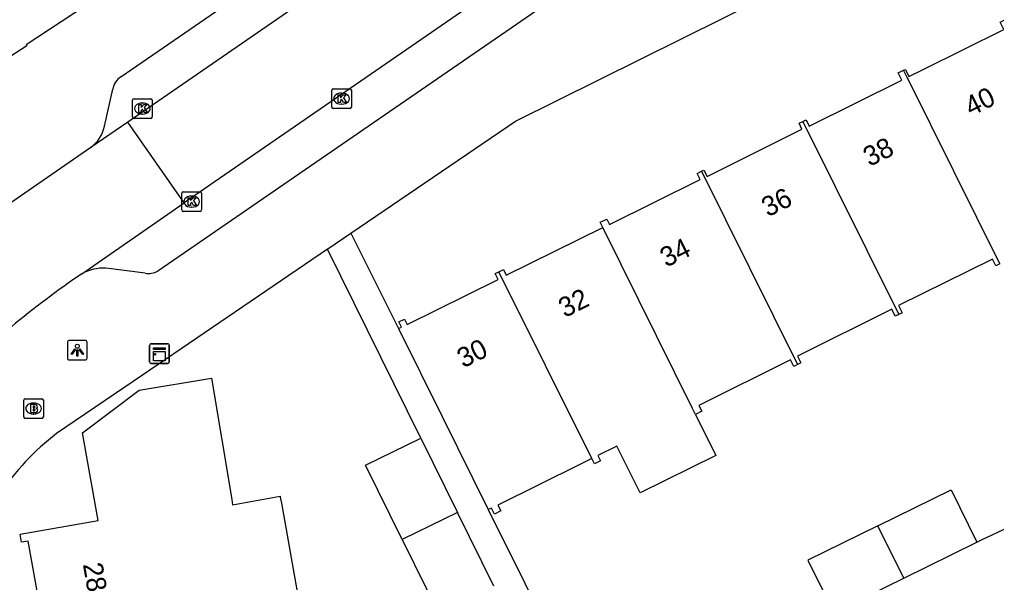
# Model space of a CAD drawing. Extents: x 157793 to 159380, y 380882 to 382313.
# Drawn here: x 158230.61 to 158280.29, y 381421.49 to 381450.14 of the extents above; entities that cross this region are included whole.
import ezdxf

# ---------------------------------------------------------------- set-up
doc = ezdxf.new("R2010")
doc.units = 0
for name, color, linetype in [('IMGEO_Brandkraan', 7, 'Continuous'), ('IMGEO_Kast', 7, 'Continuous'), ('IMGEO_Kolk', 7, 'Continuous'), ('IMGEO_Lichtpunt', 7, 'Continuous'), ('IMGEO_Pand', 7, 'Continuous'), ('IMGEO_Pand_nummerreeks', 7, 'Continuous'), ('IMGEO_Rijbaan_lokaal_open', 7, 'Continuous'), ('IMGEO_Voetpad_open', 7, 'Continuous')]:
    doc.layers.add(name, color=color, linetype=linetype)

msp = doc.modelspace()

# ---------------------------------------------------------------- linework, layer by layer
at = {"layer": 'IMGEO_Brandkraan'}
for p, q in [((158230.824, 381429.92), (158230.824, 381430.772)), ((158230.899, 381430.846), (158231.751, 381430.846)), ((158231.312, 381430.626), (158231.337, 381430.626)), ((158231.825, 381430.772), (158231.825, 381429.92)), ((158231.335, 381430.066), (158231.31, 381430.066)), ((158231.751, 381429.846), (158230.899, 381429.846))]:
    msp.add_line(p, q, dxfattribs=at)
for points in [[(158230.824, 381429.92), (158230.824, 381430.772)], [(158230.899, 381430.846), (158231.751, 381430.846)], [(158231.172, 381430.546), (158231.172, 381430.146), (158231.385, 381430.146)], [(158231.403, 381430.546), (158231.172, 381430.546)], [(158231.825, 381430.772), (158231.825, 381429.92)], [(158231.351, 381430.465), (158231.297, 381430.465), (158231.297, 381430.389)], [(158231.297, 381430.389), (158231.35, 381430.389)], [(158231.359, 381430.313), (158231.297, 381430.313), (158231.297, 381430.232)], [(158231.297, 381430.232), (158231.359, 381430.232)], [(158231.751, 381429.846), (158230.899, 381429.846)]]:
    msp.add_lwpolyline(points, dxfattribs=at)
for centre, radius, start, end in [((158230.901, 381430.77), 0.0765, 91.552, 178.448), ((158230.901, 381430.77), 0.0765, 91.552, 178.448), ((158231.407, 381430.401), 0.145, 59.4692, 91.5367), ((158231.432, 381430.448), 0.0922, 285.5137, 58.1501), ((158231.749, 381430.77), 0.0765, 1.552, 88.448), ((158231.749, 381430.77), 0.0765, 1.552, 88.448), ((158231.352, 381430.427), 0.0379, 267.8285, 90.9355), ((158231.36, 381430.272), 0.0404, 269.8759, 90.5077), ((158231.391, 381430.397), 0.251, 268.6676, 293.5347), ((158231.437, 381430.256), 0.105, 301.3115, 78.989), ((158230.901, 381429.922), 0.0765, 181.552, 268.448), ((158230.901, 381429.922), 0.0765, 181.552, 268.448), ((158231.749, 381429.922), 0.0765, 271.552, 358.448), ((158231.749, 381429.922), 0.0765, 271.552, 358.448)]:
    msp.add_arc(centre, radius, start, end, dxfattribs=at)
for centre, major_axis, ratio, start_param, end_param in [((158231.311, 381430.346), (-0.387, 0.002), 0.722429, 4.712389, 7.853982), ((158231.336, 381430.346), (-0.39, 0.002), 0.717154, 1.570796, 4.712389)]:
    msp.add_ellipse(centre, major_axis=major_axis, ratio=ratio, start_param=start_param, end_param=end_param, dxfattribs=at)
at = {"layer": 'IMGEO_Kast'}
for p, q in [((158237.228, 381432.715), (158237.228, 381433.556)), ((158237.228, 381433.556), (158237.228, 381432.715)), ((158237.303, 381433.64), (158238.144, 381433.64)), ((158238.144, 381433.64), (158237.303, 381433.64)), ((158238.228, 381433.565), (158238.228, 381432.724)), ((158238.228, 381432.724), (158238.228, 381433.565)), ((158238.153, 381432.64), (158237.312, 381432.64)), ((158237.312, 381432.64), (158238.153, 381432.64))]:
    msp.add_line(p, q, dxfattribs=at)
for points in [[(158237.423, 381433.43), (158238.023, 381433.43), (158238.023, 381433.345), (158237.423, 381433.345), (158237.423, 381433.43)], [(158237.423, 381433.255), (158238.023, 381433.255), (158238.023, 381432.766), (158237.423, 381432.766), (158237.423, 381433.255)]]:
    msp.add_lwpolyline(points, dxfattribs=at)
msp.add_circle((158237.507, 381433.104), 0.0377, dxfattribs=at)
for centre, start, end in [((158237.306, 381433.562), 92.4484, 184.2845), ((158237.306, 381433.562), 92.4484, 184.2845), ((158238.15, 381433.562), 2.4484, 94.2845), ((158238.15, 381433.562), 2.4484, 94.2845), ((158237.306, 381432.718), 182.4484, 274.2845), ((158237.306, 381432.718), 182.4484, 274.2845), ((158238.15, 381432.718), 272.4484, 4.2845), ((158238.15, 381432.718), 272.4484, 4.2845)]:
    msp.add_arc(centre, 0.0779, start, end, dxfattribs=at)
at = {"layer": 'IMGEO_Kolk'}
for p, q in [((158246.487, 381445.689), (158246.487, 381446.541)), ((158246.562, 381446.615), (158247.414, 381446.615)), ((158246.975, 381446.395), (158247, 381446.395)), ((158247.488, 381446.541), (158247.488, 381445.689)), ((158236.358, 381445.186), (158236.358, 381446.038)), ((158236.433, 381446.112), (158237.285, 381446.112)), ((158236.846, 381445.892), (158236.871, 381445.892)), ((158237.359, 381446.038), (158237.359, 381445.186)), ((158247.414, 381445.615), (158246.562, 381445.615)), ((158246.998, 381445.835), (158246.973, 381445.835)), ((158237.285, 381445.112), (158236.433, 381445.112)), ((158236.869, 381445.332), (158236.844, 381445.332)), ((158238.863, 381440.449), (158238.863, 381441.301)), ((158238.938, 381441.375), (158239.79, 381441.375)), ((158239.351, 381441.155), (158239.376, 381441.155)), ((158239.864, 381441.301), (158239.864, 381440.449)), ((158239.374, 381440.595), (158239.349, 381440.595)), ((158239.79, 381440.375), (158238.938, 381440.375))]:
    msp.add_line(p, q, dxfattribs=at)
for points in [[(158246.487, 381445.689), (158246.487, 381446.541)], [(158246.562, 381446.615), (158247.414, 381446.615)], [(158247.488, 381446.541), (158247.488, 381445.689)], [(158236.358, 381445.186), (158236.358, 381446.038)], [(158236.433, 381446.112), (158237.285, 381446.112)], [(158237.359, 381446.038), (158237.359, 381445.186)], [(158246.808, 381446.315), (158246.931, 381446.315), (158246.931, 381446.164), (158247.061, 381446.315), (158247.225, 381446.315), (158247.079, 381446.164), (158247.232, 381445.915), (158247.08, 381445.915), (158246.995, 381446.079), (158246.931, 381446.012), (158246.931, 381445.915), (158246.808, 381445.915), (158246.808, 381446.315)], [(158236.679, 381445.812), (158236.802, 381445.812), (158236.802, 381445.661), (158236.932, 381445.812), (158237.096, 381445.812), (158236.95, 381445.661), (158237.103, 381445.412), (158236.951, 381445.412), (158236.866, 381445.576), (158236.802, 381445.509), (158236.802, 381445.412), (158236.679, 381445.412), (158236.679, 381445.812)], [(158247.414, 381445.615), (158246.562, 381445.615)], [(158237.285, 381445.112), (158236.433, 381445.112)], [(158238.863, 381440.449), (158238.863, 381441.301)], [(158238.938, 381441.375), (158239.79, 381441.375)], [(158239.184, 381441.075), (158239.307, 381441.075), (158239.307, 381440.924), (158239.437, 381441.075), (158239.601, 381441.075), (158239.455, 381440.924), (158239.608, 381440.675), (158239.456, 381440.675), (158239.371, 381440.839), (158239.307, 381440.772), (158239.307, 381440.675), (158239.184, 381440.675), (158239.184, 381441.075)], [(158239.864, 381441.301), (158239.864, 381440.449)], [(158239.79, 381440.375), (158238.938, 381440.375)]]:
    msp.add_lwpolyline(points, dxfattribs=at)
for centre, start, end in [((158246.564, 381446.539), 91.552, 178.448), ((158246.564, 381446.539), 91.552, 178.448), ((158247.412, 381446.539), 1.552, 88.448), ((158247.412, 381446.539), 1.552, 88.448), ((158236.435, 381446.036), 91.552, 178.448), ((158236.435, 381446.036), 91.552, 178.448), ((158237.283, 381446.036), 1.552, 88.448), ((158237.283, 381446.036), 1.552, 88.448), ((158246.564, 381445.691), 181.552, 268.448), ((158246.564, 381445.691), 181.552, 268.448), ((158247.412, 381445.691), 271.552, 358.448), ((158247.412, 381445.691), 271.552, 358.448), ((158236.435, 381445.188), 181.552, 268.448), ((158236.435, 381445.188), 181.552, 268.448), ((158237.283, 381445.188), 271.552, 358.448), ((158237.283, 381445.188), 271.552, 358.448), ((158238.94, 381441.299), 91.552, 178.448), ((158238.94, 381441.299), 91.552, 178.448), ((158239.788, 381441.299), 1.552, 88.448), ((158239.788, 381441.299), 1.552, 88.448), ((158238.94, 381440.451), 181.552, 268.448), ((158238.94, 381440.451), 181.552, 268.448), ((158239.788, 381440.451), 271.552, 358.448), ((158239.788, 381440.451), 271.552, 358.448)]:
    msp.add_arc(centre, 0.0765, start, end, dxfattribs=at)
for centre, major_axis, ratio, start_param, end_param in [((158246.974, 381446.115), (-0.387, 0.002), 0.722429, 4.712389, 7.853982), ((158246.999, 381446.115), (-0.39, 0.002), 0.717154, 1.570796, 4.712389), ((158236.845, 381445.612), (-0.387, 0.002), 0.722429, 4.712389, 7.853982), ((158236.87, 381445.612), (-0.39, 0.002), 0.717154, 1.570796, 4.712389), ((158239.35, 381440.875), (-0.387, 0.002), 0.722429, 4.712389, 7.853982), ((158239.375, 381440.875), (-0.39, 0.002), 0.717154, 1.570796, 4.712389)]:
    msp.add_ellipse(centre, major_axis=major_axis, ratio=ratio, start_param=start_param, end_param=end_param, dxfattribs=at)
at = {"layer": 'IMGEO_Lichtpunt'}
for p, q in [((158233.05, 381433.719), (158233.05, 381432.912)), ((158233.05, 381433.719), (158233.05, 381432.912)), ((158233.952, 381433.814), (158233.144, 381433.814)), ((158233.952, 381433.814), (158233.144, 381433.814)), ((158234.046, 381432.912), (158234.046, 381433.719)), ((158234.046, 381432.912), (158234.046, 381433.719)), ((158233.144, 381432.818), (158233.952, 381432.818)), ((158233.144, 381432.818), (158233.952, 381432.818))]:
    msp.add_line(p, q, dxfattribs=at)
for points in [[(158233.424, 381433.383), (158233.463, 381433.355), (158233.275, 381433.093), (158233.237, 381433.12), (158233.424, 381433.383)], [(158233.526, 381433.335), (158233.573, 381433.335), (158233.573, 381433.013), (158233.526, 381433.013), (158233.526, 381433.335)], [(158233.636, 381433.355), (158233.674, 381433.382), (158233.861, 381433.12), (158233.822, 381433.092), (158233.636, 381433.355)]]:
    msp.add_lwpolyline(points, dxfattribs=at)
msp.add_circle((158233.549, 381433.517), 0.0994, dxfattribs=at)
for centre, start, end in [((158233.144, 381433.719), 90, 180), ((158233.144, 381433.719), 90, 180), ((158233.952, 381433.719), 0, 90), ((158233.952, 381433.719), 0, 90), ((158233.144, 381432.912), 180, 270), ((158233.144, 381432.912), 180, 270), ((158233.952, 381432.912), 270, 0), ((158233.952, 381432.912), 270, 360)]:
    msp.add_arc(centre, 0.0946, start, end, dxfattribs=at)
at = {"layer": 'IMGEO_Pand'}
for points in [[(158275.573, 381447.559), (158275.662, 381447.603), (158275.844, 381447.237), (158276.568, 381447.597), (158280.669, 381449.636), (158280.482, 381450.012), (158280.718, 381450.129), (158280.889, 381449.785)], [(158270.444, 381444.957), (158270.611, 381445.04), (158270.772, 381444.716), (158275.481, 381447.057), (158275.299, 381447.423), (158275.573, 381447.559)], [(158280.467, 381437.717), (158275.785, 381447.132), (158275.755, 381447.193), (158275.573, 381447.559)], [(158265.287, 381442.416), (158265.413, 381442.478), (158265.573, 381442.156), (158270.402, 381444.557), (158270.251, 381444.861), (158270.444, 381444.957)], [(158270.444, 381444.957), (158275.329, 381435.133)], [(158260.271, 381439.566), (158260.143, 381439.824), (158260.477, 381439.99), (158260.617, 381439.708), (158265.224, 381441.998), (158265.07, 381442.308), (158265.287, 381442.416)], [(158265.287, 381442.416), (158270.176, 381432.583)], [(158254.987, 381437.302), (158255.218, 381437.417), (158255.363, 381437.126), (158260.271, 381439.566)], [(158264.979, 381430.041), (158264.829, 381430.342), (158260.271, 381439.566)], [(158280.467, 381437.717), (158280.254, 381437.611), (158280.085, 381437.952), (158275.316, 381435.581), (158275.497, 381435.216), (158275.329, 381435.133)], [(158249.875, 381434.411), (158250.034, 381434.49), (158249.9, 381434.759), (158250.184, 381434.9), (158250.324, 381434.618), (158254.947, 381436.916), (158254.801, 381437.21), (158254.987, 381437.302)], [(158259.713, 381427.8), (158254.987, 381437.302)], [(158275.329, 381435.133), (158275.145, 381435.041), (158274.968, 381435.398), (158270.175, 381433.015), (158270.347, 381432.668), (158270.176, 381432.583)], [(158249.875, 381434.411), (158252.1, 381429.934), (158254.451, 381425.204)], [(158270.176, 381432.583), (158269.99, 381432.491), (158269.826, 381432.822), (158265.159, 381430.502), (158265.308, 381430.205), (158264.979, 381430.041)], [(158232.009, 381418.242), (158231.058, 381423.605), (158230.711, 381423.544), (158230.64, 381423.945), (158234.615, 381424.65), (158233.82, 381429.107), (158236.693, 381431.279), (158240.372, 381431.897), (158241.399, 381425.71), (158241.444, 381425.454), (158243.862, 381425.889), (158243.872, 381425.828), (158243.926, 381425.525), (158244.811, 381420.542), (158244.307, 381420.451)], [(158264.979, 381430.041), (158266.014, 381427.958), (158262.173, 381426.05), (158260.989, 381428.433), (158260.026, 381427.955), (158260.162, 381427.681), (158259.849, 381427.526), (158259.713, 381427.8)], [(158250.074, 381423.675), (158248.209, 381427.461), (158251.017, 381428.844)], [(158251.017, 381428.844), (158252.882, 381425.058)], [(158259.713, 381427.8), (158259.643, 381427.765), (158259.11, 381427.5), (158254.943, 381425.429), (158255.088, 381425.137), (158254.765, 381424.977), (158254.612, 381425.284), (158254.451, 381425.204)], [(158274.259, 381424.376), (158277.982, 381426.212), (158279.295, 381423.552)], [(158252.882, 381425.058), (158250.074, 381423.675)], [(158254.727, 381421.312), (158252.882, 381425.058)], [(158274.259, 381424.376), (158270.705, 381422.623), (158272.017, 381419.962)], [(158275.579, 381421.719), (158274.259, 381424.376)], [(158250.074, 381423.675), (158251.919, 381419.929)], [(158275.579, 381421.719), (158279.295, 381423.552)], [(158272.017, 381419.962), (158275.579, 381421.719)]]:
    msp.add_lwpolyline(points, dxfattribs=at)
at = {"layer": 'IMGEO_Rijbaan_lokaal_open'}
for points in [[(158302.02, 381483.392), (158298.335, 381481.315), (158294.12, 381478.763), (158290.279, 381476.177), (158238.977, 381440.815)], [(158287.186, 381480.143), (158236.126, 381444.916)], [(158236.126, 381444.916), (158234.237, 381443.624)], [(158238.977, 381440.815), (158236.126, 381444.916)], [(158234.237, 381443.624), (158229.108, 381440.08)], [(158233.782, 381437.207), (158238.977, 381440.815)]]:
    msp.add_lwpolyline(points, dxfattribs=at)
msp.add_arc((158261.986, 381396.021), 49.918, 124.4034, 134.7121, dxfattribs=at)
at = {"layer": 'IMGEO_Voetpad_open'}
for points in [[(158235.765, 381447.229), (158250.571, 381457.44), (158256.757, 381461.706), (158283.152, 381479.902)], [(158300.112, 381479.931), (158294.977, 381476.803), (158237.636, 381437.336)], [(158247.461, 381439.269), (158247.466, 381439.272), (158255.837, 381444.973), (158311.062, 381472.396)], [(158248.071, 381462.489), (158248.756, 381460.74), (158239.215, 381454.72), (158239.35, 381454.401), (158230.945, 381448.855), (158230.981, 381448.796), (158228.899, 381447.466), (158225.147, 381444.74)], [(158234.932, 381444.71), (158235.351, 381446.59)], [(158246.279, 381438.463), (158246.295, 381438.474), (158247.461, 381439.269)], [(158247.461, 381439.269), (158249.875, 381434.411)], [(158246.279, 381438.463), (158236.86, 381432.048), (158232.494, 381429.075)], [(158251.017, 381428.844), (158246.279, 381438.463)], [(158236.998, 381437.235), (158234.999, 381437.491)], [(158254.451, 381425.204), (158260.043, 381413.954), (158261.675, 381414.765)], [(158279.295, 381423.552), (158279.568, 381423.686), (158282.181, 381424.909)]]:
    msp.add_lwpolyline(points, dxfattribs=at)
for centre, radius, start, end in [((158236.323, 381446.414), 0.988, 124.4014, 169.7212), ((158233.068, 381445.137), 1.912, 307.6816, 347.0829), ((158234.915, 381435.101), 2.391, 87.9874, 118.2837), ((158237.179, 381438.158), 0.94, 258.905, 299.0864), ((158240.437, 381418.737), 13.037, 127.5352, 146.25)]:
    msp.add_arc(centre, radius, start, end, dxfattribs=at)

# ---------------------------------------------------------------- texts
at = {"layer": 'IMGEO_Pand_nummerreeks'}
for s, rotation, p in [('40', 26.3904, (158278.996, 381445.198)), ('38', 26.3904, (158273.832, 381442.636)), ('36', 26.3893, (158268.664, 381440.073)), ('34', 26.3893, (158263.501, 381437.511)), ('32', 26.3904, (158258.336, 381434.947)), ('30', 26.3904, (158253.178, 381432.388)), ('28', 280.0609, (158233.828, 381422.418))]:
    msp.add_text(s, height=1, rotation=rotation, dxfattribs=at).set_placement(p)

doc.saveas('drawing.dxf')
